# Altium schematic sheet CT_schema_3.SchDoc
size 421 x 351 mm
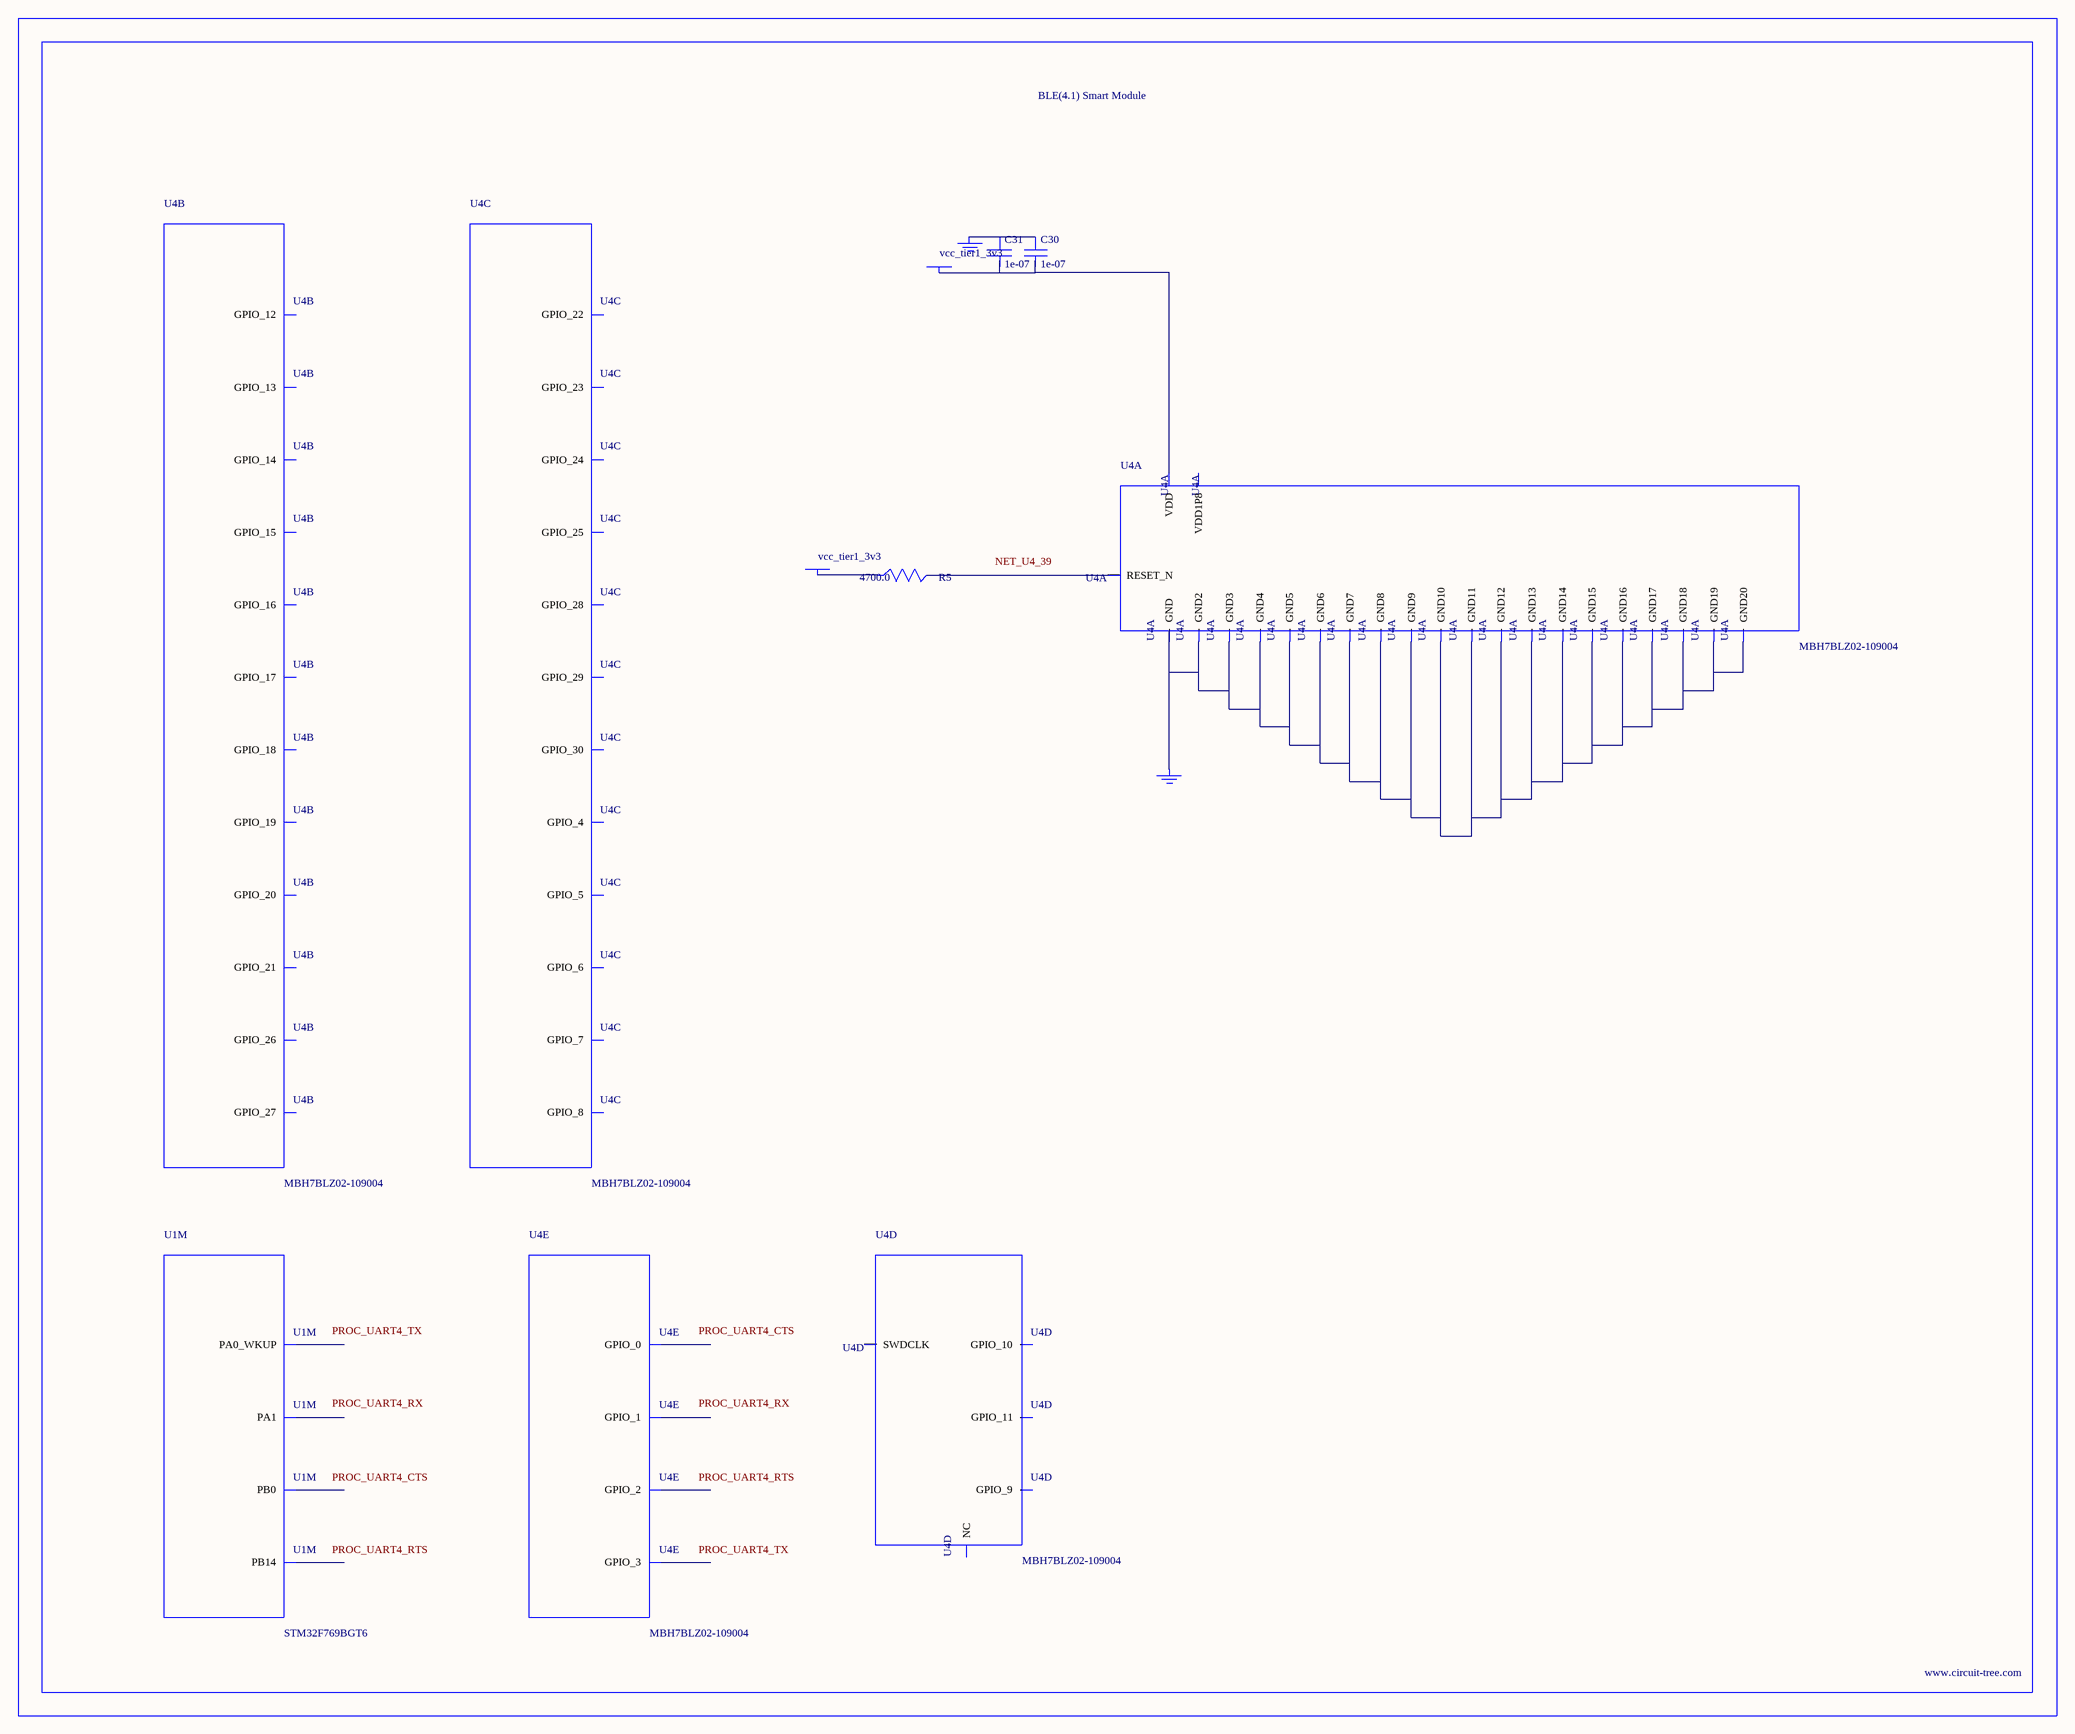
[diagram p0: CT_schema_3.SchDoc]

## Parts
BORDER2  (no value)
C30  1e-07  [C0402]
C31  1e-07  [C0402]
GND_INSTANCE_2_0  (no value)
GND_INSTANCE_2_1  (no value)
POWER_INSTANCE_2_0  vcc_tier1_3v3
POWER_INSTANCE_2_1  vcc_tier1_3v3
R5  4700.0  [R0603]
U1  STM32F769BGT6  [LQFP208]  (part M of 17)
U4  MBH7BLZ02-109004  [MBH7BLZ02-109004]  (parts A,B,C,D,E of 5)

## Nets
NetC30_1: C30.1 C31.1 GND_INSTANCE_2_0.0(GND)
NetC30_2: C30.2 C31.2 POWER_INSTANCE_2_0.0(PWR) U4.28(VDD)
NetGND_INSTANCE_2_1_0: GND_INSTANCE_2_1.0(GND) U4.1(GND) U4.3(GND2) U4.15(GND3) U4.27(GND4) U4.29(GND5) U4.41(GND6) U4.42(GND7) U4.43(GND8) U4.44(GND9) U4.45(GND10) U4.46(GND11) U4.47(GND12) U4.48(GND13) U4.49(GND14) U4.50(GND15) U4.52(GND16) U4.53(GND17) U4.54(GND18) U4.55(GND19) U4.56(GND20)
NetPOWER_INSTANCE_2_1_0: POWER_INSTANCE_2_1.0(PWR) R5.1
NetR5_2: R5.2 U4.39(RESET_N)

Not connected (* = marked no-connect by the designer): U1 43(PA0_WKUP) 44(PA1) 61(PB0) 106(PB14); U4 2(VDD1P8) 4(GPIO_17) 5(GPIO_19) 6(GPIO_18) 7(GPIO_20) 8(GPIO_16) 9(GPIO_15) 10(GPIO_14) 11(GPIO_13) 12(GPIO_12) 13(GPIO_27) 14(GPIO_26) 16(GPIO_21) 17(GPIO_22) 18(GPIO_23) 19(GPIO_24) 20(GPIO_6) 21(GPIO_5) 22(GPIO_4) 23(GPIO_3) 24(GPIO_2) 25(GPIO_1) 26(GPIO_0) 30(GPIO_25) 31(GPIO_29) 32(GPIO_28) 33(GPIO_30) 34(GPIO_7) 35(GPIO_8) 36(GPIO_9) 37(GPIO_10) 38(GPIO_11) 40(SWDCLK) 51(NC)

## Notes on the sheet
- Labels drawn without touching a wire or pin: NET_U4_39, PROC_UART4_CTS, PROC_UART4_RTS, PROC_UART4_RX, PROC_UART4_TX

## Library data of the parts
BORDER2 = BORDER_PAGE2
C30 C31 = C0402C104K3RACTU
GND_INSTANCE_2_0 GND_INSTANCE_2_1 = GND
POWER_INSTANCE_2_0 POWER_INSTANCE_2_1 = PWR
R5 = RC0603JR-074K7L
